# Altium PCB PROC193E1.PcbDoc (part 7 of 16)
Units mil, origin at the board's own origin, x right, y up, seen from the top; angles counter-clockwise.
Board outline 7700 x 2300 mil, 6 copper layers (Top Layer, GND 1, SIG 1, PWR, GND 2, Bottom Layer), stack 60.98 mil thick; 946 components, 667 nets, 9401 pads, 1730 vias.
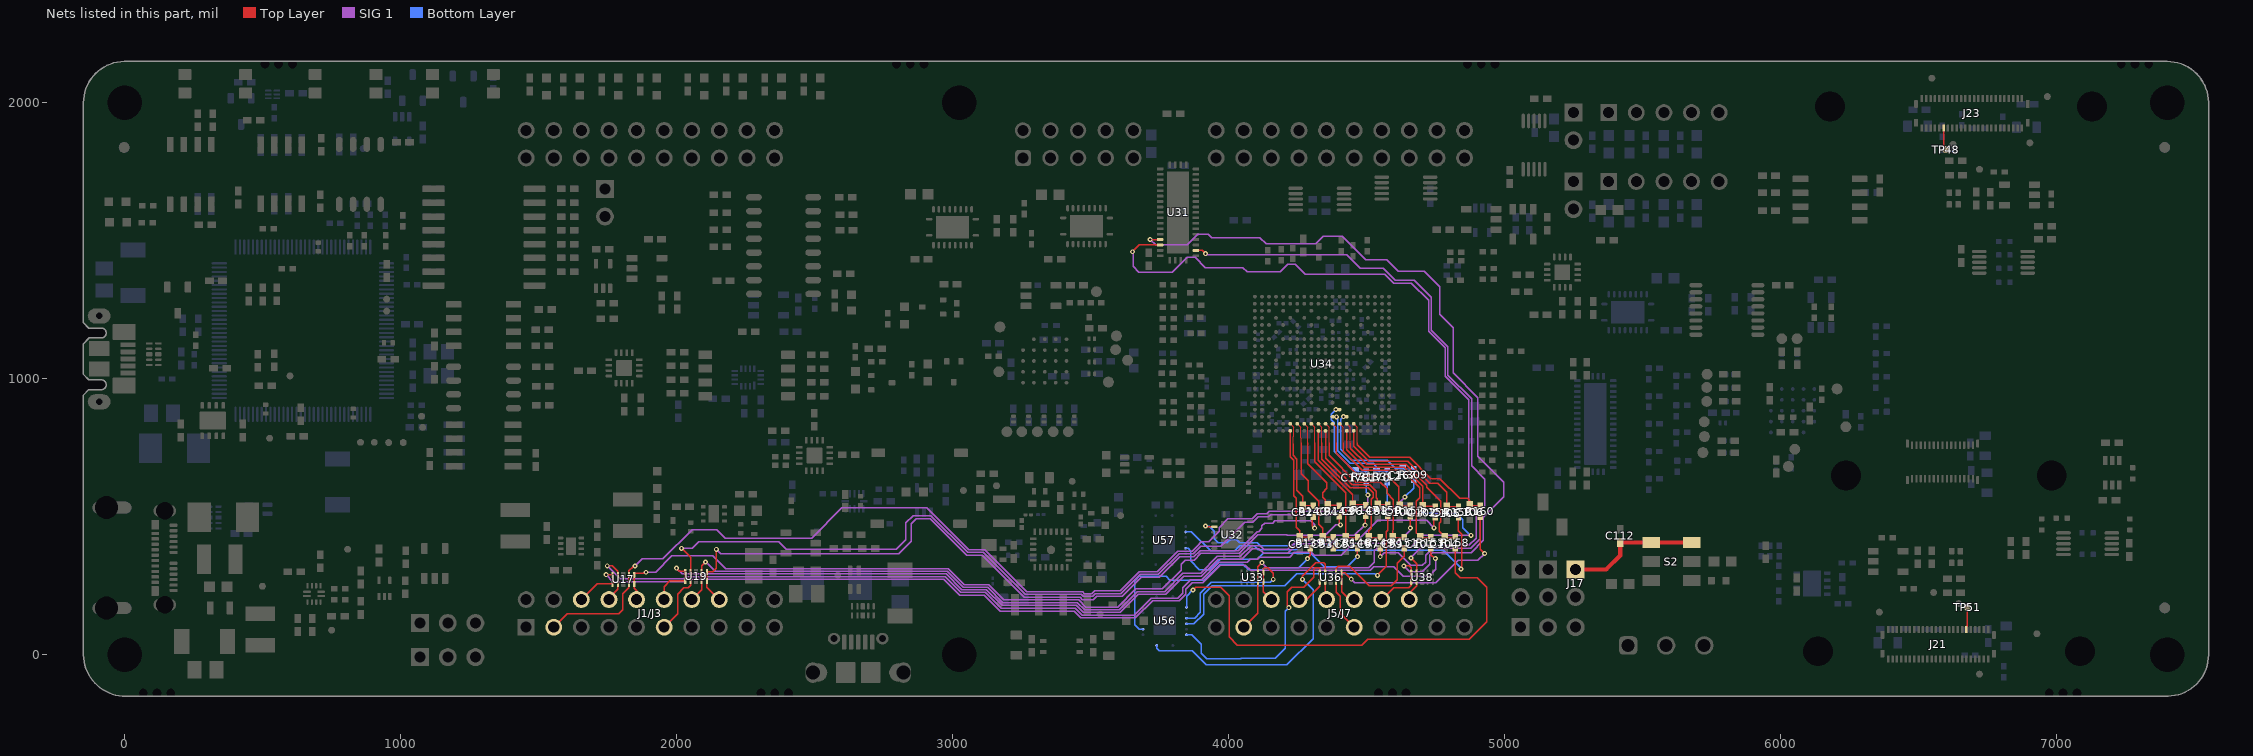
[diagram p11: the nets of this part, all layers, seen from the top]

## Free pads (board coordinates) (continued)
  round 4 on Mech16: 1(6059,2058) 1(6062.04,463.96) 1(6062.04,463.96) 1(6065.44,675.6) 1(6065.44,675.6) 1(6076,-115) 1(6076,-115) 1(6079.36,431.43) 1(6079.36,431.43) 1(6080.43,754.51) 1(6080.43,754.51) 1(6089.46,1050.69) 1(6089.46,1050.69) 1(6097.5,1257.86) 1(6097.5,1257.86) 1(6100.62,935.27) 1(6100.62,935.27) 1(6101.18,1357.83) 1(6101.18,1357.83) 1(6111,2109) 1(6111,2109) 1(6117.93,423.12) 1(6117.93,423.12) 1(6135.75,360.14) 1(6135.75,360.14) 1(6140,813) 1(6140,813) 1(6152.64,1260.32) 1(6152.64,1260.32) 1(6152.82,882.49) 1(6152.82,882.49) 1(6168.23,1013.42) 1(6168.23,1013.42) 1(6172.35,963.43) 1(6172.35,963.43) 1(6172.8,923.81) 1(6172.8,923.81) 1(6176,-115) 1(6176,-115) 1(6187,1583) 1(6187,1583) 1(6197.24,1674.12) 1(6197.24,1674.12) 1(6207.67,1013.42) 1(6207.67,1013.42) 1(6208.6,871.42) 1(6208.6,871.42) 1(6218,1593) 1(6218,1593) 1(6220.27,1553.27) 1(6220.27,1553.27) 1(6220.63,922.47) 1(6220.63,922.47) 1(6220.63,1211.87) 1(6220.63,1211.87) 1(6222.32,1172.87) 1(6222.32,1172.87) 1(6237.78,1675.15) 1(6237.78,1675.15) 1(6244.74,1374.44) 1(6244.74,1374.44) 1(6254.09,277.4) 1(6254.09,277.4) 1(6255,242) 1(6255,242) 1(6263.22,363.2) 1(6263.22,363.2) 1(6265.78,825.03) 1(6265.78,825.03) 1(6266.12,1223.61) 1(6266.12,1223.61) 1(6276,-115) 1(6276,-115) 1(6281,1538) 1(6281,1538) 1(6287.3,329.4) 1(6287.3,329.4) 1(6291.66,260.9) 1(6291.66,260.9) 1(6293.61,297.39) 1(6293.61,297.39) 1(6305,1762) 1(6305,1762) 1(6311,2109) 1(6311,2109) 1(6314,903) 1(6314,903) 1(6321.24,968.9) 1(6321.24,968.9) 1(6321.24,1051.32) 1(6321.24,1051.32) 1(6321.24,1151.35) 1(6321.24,1151.35) 1(6342.31,-83.37) 1(6342.31,-83.37) 1(6343,1641) 1(6343,1641) 1(6343.71,811.42) 1(6343.71,811.42) 1(6343.79,-42.49) 1(6343.79,-42.49) 1(6351.26,1608.66) 1(6351.26,1608.66) 1(6351.66,1578.24) 1(6351.66,1578.24) 1(6357.97,1758.31) 1(6357.97,1758.31) 1(6362,119.39) 1(6362,119.39) 1(6369.13,780.23) 1(6369.13,780.23) 1(6371.94,1649.6) 1(6371.94,1649.6) 1(6383.42,1161.63) 1(6383.42,1161.63) 1(6389,1048) 1(6389,1048) 1(6393.82,1330.03) 1(6393.82,1330.03) 1(6396,967) 1(6396,967) 1(6407.29,918.98) 1(6407.29,918.98) 1(6409.99,147.31) 1(6409.99,147.31) 1(6410.25,1007.84) 1(6410.25,1007.84) 1(6411.01,120.55) 1(6411.01,120.55) 1(6417.81,-87.19) 1(6417.81,-87.19) 1(6417.83,-45.04) 1(6417.83,-45.04) 1(6418.5,1875.1) 1(6418.5,1875.1) 1(6418.93,1091.76) 1(6418.93,1091.76) 1(6422.74,1913.01) 1(6422.74,1913.01) 1(6431.32,461.4) 1(6431.32,461.4) 1(6439.12,418.45) 1(6439.12,418.45) 1(6440.36,632.65) 1(6440.36,632.65) 1(6442.1,792.77) 1(6442.1,792.77) 1(6447.51,132.59) 1(6447.51,132.59) 1(6451.72,-47.64) 1(6451.72,-47.64) 1(6457.15,-87.19) 1(6457.15,-87.19) 1(6460.16,1871.6) 1(6460.16,1871.6) 1(6462.05,63) 1(6462.05,63) 1(6472.29,1331.83) 1(6472.29,1331.83) 1(6483.21,-47.64) 1(6483.21,-47.64) 1(6483.89,-87.19) 1(6483.89,-87.19) 1(6483.89,123.73) 1(6483.89,123.73) 1(6496.77,289.56) 1(6496.77,289.56) 1(6496.77,418.65) 1(6496.77,418.65) 1(6508.62,2104.04) 1(6508.62,2104.04) 1(6512.08,791.6) 1(6512.08,791.6) 1(6512.17,239.5) 1(6512.17,239.5) 1(6514.68,-87.19) 1(6514.68,-87.19) 1(6514.71,-47.64) 1(6514.71,-47.64) 1(6515.41,176.47) 1(6515.41,176.47) 1(6516,1502) 1(6516,1502) 1(6519,1768) 1(6519,1768) 1(6521.05,65) 1(6521.05,65) 1(6534.11,1852.25) 1(6534.11,1852.25) 1(6534.11,1879.65) 1(6534.11,1879.65) 1(6546.18,-87.19) 1(6546.18,-87.19) 1(6546.21,-47.64) 1(6546.21,-47.64) 1(6546.88,123.73) 1(6546.88,123.73) 1(6546.91,176.47) 1(6546.91,176.47) 1(6547.26,290.98) 1(6547.26,290.98) 1(6547.26,418.65) 1(6547.26,418.65) 1(6558.45,2049.91) 1(6558.45,2049.91) 1(6569.88,669.39) 1(6569.88,669.39) 1(6572.19,1789.93) 1(6572.19,1789.93) 1(6577.67,-87.19) 1(6577.67,-87.19) 1(6577.7,-47.64) 1(6577.7,-47.64) 1(6577.74,63.37) 1(6577.74,63.37) 1(6578.41,176.47) 1(6578.41,176.47) 1(6585.33,1951.64) 1(6585.33,1951.64) 1(6590.01,2090) 1(6590.01,2090) 1(6605.57,727.93) 1(6605.57,727.93) 1(6608,686) 1(6608,686) 1(6609.2,-47.64) 1(6609.2,-47.64) 1(6609.87,123.73) 1(6609.87,123.73) 1(6617.38,788.61) 1(6617.38,788.61) 1(6621.15,2090) 1(6621.15,2090) 1(6621.44,1879.92) 1(6621.44,1879.92) 1(6625.22,2049.35) 1(6625.22,2049.35) 1(6625.88,1950.65) 1(6625.88,1950.65) 1(6633.88,66.89) 1(6633.88,66.89) 1(6633.94,729.5) 1(6633.94,729.5) 1(6635.54,824.27) 1(6635.54,824.27) 1(6635.94,532.44) 1(6635.94,532.44) 1(6639.05,9) 1(6639.05,9) 1(6639.84,-80.81) 1(6639.84,-80.81) 1(6643.94,677.87) 1(6643.94,677.87) 1(6644.87,128.8) 1(6644.87,128.8) 1(6650,1827) 1(6650,1827) 1(6650.64,598.7) 1(6650.64,598.7) 1(6651.32,871.42) 1(6651.32,871.42) 1(6651.86,1503.22) 1(6651.86,1503.22) 1(6652.94,1879.92) 1(6652.94,1879.92) 1(6652.94,2050.04) 1(6652.94,2050.04) 1(6653,2090) 1(6653,2090) 1(6655.1,1387.02) 1(6655.1,1387.02) 1(6664.63,1131.82) 1(6664.63,1131.82) 1(6672.19,-47.64) 1(6672.19,-47.64) 1(6681.59,416.99) 1(6681.59,416.99) 1(6684.43,1879.92) 1(6684.43,1879.92) 1(6684.43,2050.04) 1(6684.43,2050.04) 1(6685.41,-86.1) 1(6685.41,-86.1) 1(6689,1834) 1(6689,1834) 1(6691.19,597.33) 1(6691.19,597.33) 1(6699.81,2090) 1(6699.81,2090) 1(6700.06,817.65) 1(6700.06,817.65) 1(6703.69,-47.64) 1(6703.69,-47.64) 1(6707.93,1713.56) 1(6707.93,1713.56) 1(6708.05,1592.26) 1(6708.05,1592.26) 1(6709.9,540.63) 1(6709.9,540.63) 1(6713.26,691.55) 1(6713.26,691.55) 1(6715.93,1801.72) 1(6715.93,1801.72) 1(6715.93,2049.35) 1(6715.93,2049.35) 1(6720,1337) 1(6720,1337) 1(6720.46,1108.48) 1(6720.46,1108.48) 1(6732.91,2090) 1(6732.91,2090) 1(6735.18,-47.64) 1(6735.18,-47.64) 1(6736.23,206.96) 1(6736.23,206.96) 1(6741,1946) 1(6741,1946) 1(6742.9,1823.8) 1(6742.9,1823.8) 1(6747.43,1879.92) 1(6747.43,1879.92) 1(6758.52,1713.44) 1(6758.52,1713.44) 1(6758.89,1588.61) 1(6758.89,1588.61) 1(6761.47,1847.69) 1(6761.47,1847.69) 1(6761.95,1369.47) 1(6761.95,1369.47) 1(6761.95,1402.77) 1(6761.95,1402.77) 1(6761.95,1441.9) 1(6761.95,1441.9) 1(6762.9,-78.84) 1(6762.9,-78.84) 1(6766.07,1476.9) 1(6766.07,1476.9) 1(6766.31,138.94) 1(6766.31,138.94) 1(6769.25,2050.35) 1(6769.25,2050.35) 1(6771,1772.8) 1(6771,1772.8) 1(6782.48,1949.68) 1(6782.48,1949.68) 1(6791.42,411.53) 1(6791.42,411.53) 1(6809.27,2089.76) 1(6809.27,2089.76) 1(6810.42,1879.92) 1(6810.42,1879.92) 1(6811.11,2050.04) 1(6811.11,2050.04) 1(6818,1843) 1(6818,1843) 1(6832.64,436.83) 1(6832.64,436.83) 1(6838,-113) 1(6838,-113) 1(6839.9,1992.32) 1(6839.9,1992.32) 1(6840.77,2089.76) 1(6840.77,2089.76) 1(6843.41,-47.3) 1(6843.41,-47.3) 1(6843.41,-12.15) 1(6843.41,-12.15) 1(6849.07,1875.92) 1(6849.07,1875.92) 1(6858.43,1349.46) 1(6858.43,1349.46) 1(6858.47,1497.59) 1(6858.47,1497.59) 1(6861.42,1849.7) 1(6861.42,1849.7) 1(6863.87,411.52) 1(6863.87,411.52) 1(6867.77,32.51) 1(6867.77,32.51) 1(6872.26,2089.76) 1(6872.26,2089.76) 1(6873.87,2050.5) 1(6873.87,2050.5) 1(6890.54,497.35) 1(6890.54,497.35) 1(6893,1962) 1(6893,1962) 1(6920.45,451.78) 1(6920.45,451.78) 1(6935.36,1422.22) 1(6935.36,1422.22) 1(6938,-113) 1(6938,-113) 1(6946,880) 1(6946,880) 1(6952,1154) 1(6952,1154) 1(6956.66,1703.75) 1(6956.66,1703.75) 1(6959.69,1387.53) 1(6959.69,1387.53) 1(6968.01,1907.59) 1(6968.01,1907.59) 1(6968.01,1949.02) 1(6968.01,1949.02) 1(6968.01,1987.22) 1(6968.01,1987.22) 1(6972.59,444.64) 1(6972.59,444.64) 1(6979.72,2110.52) 1(6979.72,2110.52) 1(6979.88,402.4) 1(6979.88,402.4) 1(6983.36,1422.45) 1(6983.36,1422.45) 1(7007.95,1669.53) 1(7007.95,1669.53) 1(7009.05,1630.16) 1(7009.05,1630.16) 1(7019.86,1504.79) 1(7019.86,1504.79) 1(7020.13,1553) 1(7020.13,1553) 1(7060.19,486.26) 1(7060.19,486.26) 1(7091.5,472.45) 1(7091.5,472.45) 1(7091.56,332.08) 1(7091.56,332.08) 1(7124.57,560.92) 1(7124.57,560.92) 1(7137.93,768.73) 1(7137.93,768.73) 1(7155.31,396.62) 1(7155.31,396.62) 1(7155.63,441.85) 1(7155.63,441.85) 1(7155.69,364.01) 1(7155.69,364.01) 1(7214.27,524.94) 1(7214.27,524.94) 1(7218,-110) 1(7218,-110) 1(7223.87,807.38) 1(7223.87,807.38) 1(7225.52,738.31) 1(7225.52,738.31) 1(7264.66,615.29) 1(7264.66,615.29) 1(7265.02,516.76) 1(7265.02,516.76) 1(7275.03,706.65) 1(7275.03,706.65) 1(7295.19,356.43) 1(7295.19,356.43) 1(7295.19,403.19) 1(7295.19,403.19) 1(7295.79,452.47) 1(7295.79,452.47) 1(7457,1861) 1(7457,1861) 1(7459,168) 1(7459,168) 1(7459,268) 1(7459,268) 1(7459,368) 1(7459,368) 1(7459,468) 1(7459,468) 1(7459,568) 1(7459,568) 1(7459,668) 1(7459,668) 1(7459,768) 1(7459,768) 1(7459,868) 1(7459,868) 1(7459,968) 1(7459,968) 1(7459,1068) 1(7459,1068) 1(7459,1168) 1(7459,1168) 1(7459,1268) 1(7459,1268) 1(7459,1368) 1(7459,1368) 1(7459,1468) 1(7459,1468) 1(7459,1568) 1(7459,1568) 1(7459,1668) 1(7459,1668) 1(7459,1768) 1(7459,1768) 1(7515,121) 1(7515,121) 1(7515,221) 1(7515,221) 1(7515,321) 1(7515,321) 1(7515,421) 1(7515,421) 1(7515,521) 1(7515,521) 1(7515,621) 1(7515,621) 1(7515,721) 1(7515,721) 1(7515,821) 1(7515,821) 1(7515,921) 1(7515,921) 1(7515,1021) 1(7515,1021) 1(7515,1121) 1(7515,1121) 1(7515,1221) 1(7515,1221) 1(7515,1321) 1(7515,1321) 1(7515,1421) 1(7515,1421) 1(7515,1521) 1(7515,1521) 1(7515,1621) 1(7515,1621) 1(7515,1721) 1(7515,1721) 1(7515,1821) 1(7515,1821)
  round 63 on Mech16: 1(0,0) 1(0,0) 1(0,2000) 1(0,2000) 1(3023.18,0) 1(3023.18,0) 1(3023.18,2000) 1(3023.18,2000) 1(7400,0) 1(7400,0) 1(7400,2000) 1(7400,2000)
  round 31.5 on Mech16: 1(0,0) 1(0,2000) 1(3023.18,0) 1(3023.18,2000) 1(7400,0) 1(7400,2000)
  round 3 on Mech16: 1(41.79,-148.2) 1(41.79,-148.2) 1(41.79,-148.2) 1(41.79,-148.2) 1(191.4,-148.2) 1(191.4,-148.2) 1(191.4,-148.2) 1(191.4,-148.2) 1(482.59,2150.26) 1(482.59,2150.26) 1(632.19,2150.26) 1(632.19,2150.26) 1(2279.79,-148.2) 1(2279.79,-148.2) 1(2429.4,-148.2) 1(2429.4,-148.2) 1(2771.26,2150.26) 1(2771.26,2150.26) 1(2920.86,2150.26) 1(2920.86,2150.26) 1(4517.79,-148.2) 1(4517.79,-148.2) 1(4667.4,-148.2) 1(4667.4,-148.2) 1(4839.92,2150.26) 1(4839.92,2150.26) 1(4989.53,2150.26) 1(4989.53,2150.26) 1(6947.79,-148.2) 1(6947.79,-148.2) 1(7097.4,-148.2) 1(7097.4,-148.2) 1(7208.59,2150.26) 1(7208.59,2150.26) 1(7208.59,2150.26) 1(7208.59,2150.26) 1(7247.96,2189.63) 1(7247.96,2189.63) 1(7247.96,2189.63) 1(7247.96,2189.63) 1(7318.82,2189.63) 1(7318.82,2189.63) 1(7318.82,2189.63) 1(7318.82,2189.63) 1(7358.19,2150.26) 1(7358.19,2150.26) 1(7358.19,2150.26) 1(7358.19,2150.26)
  round 1.5 on Mech16: 1(41.79,-148.2) 1(41.79,-148.2) 1(191.4,-148.2) 1(191.4,-148.2) 1(482.59,2150.26) 1(632.19,2150.26) 1(2279.79,-148.2) 1(2429.4,-148.2) 1(2771.26,2150.26) 1(2920.86,2150.26) 1(4517.79,-148.2) 1(4667.4,-148.2) 1(4839.92,2150.26) 1(4989.53,2150.26) 1(6947.79,-148.2) 1(7097.4,-148.2) 1(7208.59,2150.26) 1(7208.59,2150.26) 1(7247.96,2189.63) 1(7247.96,2189.63) 1(7318.82,2189.63) 1(7318.82,2189.63) 1(7358.19,2150.26) 1(7358.19,2150.26)
  round 16 on Mech16: 1(66.59,-138.2) 1(66.59,-138.2) 1(116.59,-138.2) 1(116.59,-138.2) 1(166.59,-138.2) 1(166.59,-138.2) 1(507.39,2140.26) 1(507.39,2140.26) 1(557.39,2140.26) 1(557.39,2140.26) 1(607.39,2140.26) 1(607.39,2140.26) 1(2304.59,-138.2) 1(2304.59,-138.2) 1(2354.59,-138.2) 1(2354.59,-138.2) 1(2404.59,-138.2) 1(2404.59,-138.2) 1(2796.06,2140.26) 1(2796.06,2140.26) 1(2846.06,2140.26) 1(2846.06,2140.26) 1(2896.06,2140.26) 1(2896.06,2140.26) 1(4542.59,-138.2) 1(4542.59,-138.2) 1(4592.59,-138.2) 1(4592.59,-138.2) 1(4642.59,-138.2) 1(4642.59,-138.2) 1(4864.73,2140.26) 1(4864.73,2140.26) 1(4914.73,2140.26) 1(4914.73,2140.26) 1(4964.73,2140.26) 1(4964.73,2140.26) 1(6972.59,-138.2) 1(6972.59,-138.2) 1(7022.59,-138.2) 1(7022.59,-138.2) 1(7072.59,-138.2) 1(7072.59,-138.2) 1(7233.39,2140.26) 1(7233.39,2140.26) 1(7283.39,2140.26) 1(7283.39,2140.26) 1(7333.39,2140.26) 1(7333.39,2140.26)
  round 8 on Mech16: 1(66.59,-138.2) 1(116.59,-138.2) 1(166.59,-138.2) 1(507.39,2140.26) 1(557.39,2140.26) 1(607.39,2140.26) 1(2304.59,-138.2) 1(2354.59,-138.2) 1(2404.59,-138.2) 1(2796.06,2140.26) 1(2846.06,2140.26) 1(2896.06,2140.26) 1(4542.59,-138.2) 1(4592.59,-138.2) 1(4642.59,-138.2) 1(4864.73,2140.26) 1(4914.73,2140.26) 1(4964.73,2140.26) 1(6972.59,-138.2) 1(7022.59,-138.2) 1(7072.59,-138.2) 1(7233.39,2140.26) 1(7283.39,2140.26) 1(7333.39,2140.26)
  round 7.87 on Mech16: 1(112.87,1053.49) 1(1595.06,417.3) 1(1771.11,265.47) 1(2034.38,276.01) 1(2158.71,486.82) 1(2638.57,151.52) 1(4050.48,273.46) 1(4404.52,289.21) 1(4735.74,289.21)
  round 15.75 on Mech16: 1(112.87,1053.49) 1(314.58,461.84) 1(1168.63,1097.63) 1(1595.06,417.3) 1(1771.11,265.47) 1(2034.38,276.01) 1(2158.71,486.82) 1(2280.62,983.5) 1(2638.57,151.52) 1(2669.41,536.84) 1(4002.75,671.68) 1(4050.48,273.46) 1(4404.52,289.21) 1(4735.74,289.21)
  round 11.81 on Mech16: 1(280.3,807.97) 1(455.07,539.37) 1(665.88,240.37) 1(1848.5,1010.01) 1(2459.32,751.68) 1(2655.9,243.94) 1(2936.96,1510.69) 1(3422.65,1514.81) 1(3981.31,489.61) 1(5247.89,1356.69) 1(5446.96,33.86) 1(5584.76,33.86) 1(5722.55,33.86) 1(6140.07,1722.87)
  round 23.62 on Mech16: 1(280.3,807.97) 1(405.34,934.21) 1(1848.5,1010.01) 1(2459.32,751.68) 1(2936.96,1510.69) 1(3422.65,1514.81) 1(3981.31,489.61) 1(5247.89,1356.69) 1(5446.96,33.86) 1(5446.96,33.86) 1(5507.5,1203.01) 1(5584.76,33.86) 1(5584.76,33.86) 1(5722.55,33.86) 1(5722.55,33.86) 1(6140.07,1722.87) 1(6153.46,296.1)
  round 3.94 on Mech16: 1(281.29,848.32) 1(281.29,848.32) 1(318.69,825.68) 1(318.69,825.68) 1(318.69,870.96) 1(318.69,870.96) 1(356.09,848.32) 1(356.09,848.32) 1(1616.72,372.03) 1(1616.72,372.03) 1(1616.72,415.33) 1(1616.72,415.33) 1(1790.43,1020.84) 1(1790.43,1020.84) 1(1790.43,1058.24) 1(1790.43,1058.24) 1(1827.83,1020.84) 1(1827.83,1020.84) 1(1827.83,1058.24) 1(1827.83,1058.24) 1(2134.1,488.78) 1(2134.1,488.78) 1(2134.1,532.09) 1(2134.1,532.09) 1(2479.99,703.45) 1(2479.99,703.45) 1(2479.99,740.85) 1(2479.99,740.85) 1(2517.39,703.45) 1(2517.39,703.45) 1(2517.39,740.85) 1(2517.39,740.85) 1(2948.77,1549.07) 1(2948.77,1549.07) 1(2998.97,1518.56) 1(2998.97,1518.56) 1(2998.97,1579.58) 1(2998.97,1579.58) 1(3049.17,1549.07) 1(3049.17,1549.07) 1(3340.16,378.98) 1(3340.16,378.98) 1(3371.74,378.98) 1(3371.74,378.98) 1(3434.46,1553.2) 1(3434.46,1553.2) 1(3484.65,1522.69) 1(3484.65,1522.69) 1(3484.65,1583.71) 1(3484.65,1583.71) 1(3534.85,1553.2) 1(3534.85,1553.2) 1(3785.57,1510.85) 1(3785.57,1510.85) 1(3785.57,1556.91) 1(3785.57,1556.91) 1(3785.57,1602.98) 1(3785.57,1602.98) 1(3785.57,1649.04) 1(3785.57,1649.04) 1(3785.57,1695.1) 1(3785.57,1695.1) 1(3816.08,1464.79) 1(3816.08,1464.79) 1(3816.08,1510.85) 1(3816.08,1510.85) 1(3816.08,1556.91) 1(3816.08,1556.91) 1(3816.08,1602.98) 1(3816.08,1602.98) 1(3816.08,1649.04) 1(3816.08,1649.04) 1(3816.08,1695.1) 1(3816.08,1695.1) 1(3816.08,1741.16) 1(3816.08,1741.16) 1(3846.59,1510.85) 1(3846.59,1510.85) 1(3846.59,1556.91) 1(3846.59,1556.91) 1(3846.59,1602.98) 1(3846.59,1602.98) 1(3846.59,1649.04) 1(3846.59,1649.04) 1(3846.59,1695.1) 1(3846.59,1695.1) 1(3985.24,434.49) 1(3985.24,434.49) 1(4012.8,397.09) 1(4012.8,397.09) 1(4012.8,471.9) 1(4012.8,471.9) 1(4040.36,434.49) 1(4040.36,434.49) 1(5189.82,1367.51) 1(5189.82,1367.51) 1(5189.82,1404.91) 1(5189.82,1404.91) 1(5227.22,1367.51) 1(5227.22,1367.51) 1(5227.22,1404.91) 1(5227.22,1404.91) 1(5297.57,743.9) 1(5297.57,743.9) 1(5297.57,789.97) 1(5297.57,789.97) 1(5297.57,836.03) 1(5297.57,836.03) 1(5297.57,882.09) 1(5297.57,882.09) 1(5297.57,928.16) 1(5297.57,928.16) 1(5328.08,697.84) 1(5328.08,697.84) 1(5328.08,743.9) 1(5328.08,743.9) 1(5328.08,789.97) 1(5328.08,789.97) 1(5328.08,836.03) 1(5328.08,836.03) 1(5328.08,882.09) 1(5328.08,882.09) 1(5328.08,928.16) 1(5328.08,928.16) 1(5328.08,974.22) 1(5328.08,974.22) 1(5358.59,743.9) 1(5358.59,743.9) 1(5358.59,789.97) 1(5358.59,789.97) 1(5358.59,836.03) 1(5358.59,836.03) 1(5358.59,882.09) 1(5358.59,882.09) 1(5358.59,928.16) 1(5358.59,928.16) 1(5395.29,1241.4) 1(5395.29,1241.4) 1(5445.49,1210.89) 1(5445.49,1210.89) 1(5445.49,1271.91) 1(5445.49,1271.91) 1(5495.68,1241.4) 1(5495.68,1241.4) 1(6090.47,257.71) 1(6090.47,257.71) 1(6113.11,220.31) 1(6113.11,220.31) 1(6113.11,295.11) 1(6113.11,295.11) 1(6135.75,257.71) 1(6135.75,257.71)
  round 1.25 on Mech16: 1(462.14,247.07) 1(501.86,784.53) 1(507.91,247.07) 1(547.63,784.53) 1(575.59,1010.35) 1(621.36,1010.35) 1(755.63,1668.93) 1(755.63,1812.54) 1(760.59,1663.96) 1(760.59,1817.51) 1(779.13,1718.96) 1(779.13,1718.96) 1(826.13,1718.96) 1(826.13,1718.96) 1(831.01,770) 1(857.12,1755) 1(876.78,770) 1(881.01,770) 1(902.88,1755) 1(926.78,770) 1(933.01,769) 1(943.58,1663.96) 1(943.58,1817.51) 1(948.54,1668.93) 1(948.54,1812.54) 1(978.78,769) 1(986.01,769) 1(1031.78,769) 1(1034.14,865) 1(1066.1,302.44) 1(1066.1,359.48) 1(1069.06,299.46) 1(1069.06,362.46) 1(1079.91,865) 1(1092.12,779.89) 1(1137.88,779.89) 1(1178.14,299.46) 1(1178.14,362.46) 1(1181.1,302.44) 1(1181.1,359.48) 1(1223.15,877.09) 1(1223.15,1060.08) 1(1228.11,872.13) 1(1228.11,1065.04) 1(1278.15,994.54) 1(1278.15,994.54) 1(1278.15,1041.54) 1(1278.15,1041.54) 1(1371.73,872.13) 1(1371.73,1065.04) 1(1376.69,877.09) 1(1376.69,1060.08) 1(1687.12,698.96) 1(1732.88,698.96) 1(1860.44,1344.77) 1(1860.44,1453.85) 1(1863.43,1341.81) 1(1863.43,1456.81) 1(1920.46,1341.81) 1(1920.46,1456.81) 1(1923.44,1344.77) 1(1923.44,1453.85) 1(2309.67,1292.52) 1(2309.67,1672.56) 1(2314.65,1287.54) 1(2314.65,1677.54) 1(2408.67,1311.04) 1(2408.67,1311.04) 1(2408.67,1358.04) 1(2408.67,1358.04) 1(2417.86,350.97) 1(2417.86,460.05) 1(2420.84,348.01) 1(2420.84,463.01) 1(2458.69,1287.54) 1(2458.69,1677.54) 1(2463.67,1292.52) 1(2463.67,1672.56) 1(2477.88,348.01) 1(2477.88,463.01) 1(2480.86,350.97) 1(2480.86,460.05) 1(2540.46,333.41) 1(2586.23,333.41) 1(2629.52,1710.51) 1(2675.29,1710.51) 1(2704.37,1715) 1(2750.14,1715) 1(3287.95,1246.22) 1(3287.95,1355.31) 1(3290.93,1243.26) 1(3290.93,1358.26) 1(3347.97,1243.26) 1(3347.97,1358.26) 1(3350.95,1246.22) 1(3350.95,1355.31) 1(3584.12,504) 1(3629.88,504) 1(4270.93,1705.67) 1(4270.93,1597.45) 1(4275.83,1710.56) 1(4275.83,1592.56) 1(4353.93,1613.56) 1(4381.93,1613.56) 1(4384.04,1592.56) 1(4384.04,1710.56) 1(4388.93,1597.45) 1(4388.93,1705.67) 1(4582.91,1636.42) 1(4582.91,1744.64) 1(4587.8,1631.53) 1(4587.8,1749.53) 1(4589.91,1728.53) 1(4617.91,1728.53) 1(4696.02,1631.53) 1(4696.02,1749.53) 1(4700.91,1636.42) 1(4700.91,1744.64) 1(4882.95,1523.67) 1(4882.95,1632.75) 1(4885.94,1520.71) 1(4885.94,1635.71) 1(4942.97,1520.71) 1(4942.97,1635.71) 1(4945.95,1523.67) 1(4945.95,1632.75) 1(5007.75,1531.58) 1(5007.75,1588.62) 1(5010.7,1528.6) 1(5010.7,1591.6) 1(5047.48,1792.54) 1(5047.48,1900.76) 1(5052.37,1787.65) 1(5052.37,1905.65) 1(5068.48,1794.65) 1(5068.48,1822.65) 1(5119.79,1528.6) 1(5119.79,1591.6) 1(5122.75,1531.58) 1(5122.75,1588.62) 1(5160.58,1787.65) 1(5160.58,1905.65) 1(5165.48,1792.54) 1(5165.48,1900.76) 1(5717.83,1158.94) 1(5717.83,1340.05) 1(5725.71,1151.07) 1(5725.71,1347.92) 1(5757.2,1292.8) 1(5757.2,1292.8) 1(5757.2,1324.3) 1(5757.2,1324.3) 1(5883.19,1151.07) 1(5883.19,1347.92) 1(5891.06,1158.94) 1(5891.06,1340.05) 1(5915.25,1363.04) 1(5955.53,944.72) 1(5961.02,1363.04) 1(6001.3,944.72) 1(6357.35,392.16) 1(6357.35,283.08) 1(6360.33,395.12) 1(6360.33,280.12) 1(6417.36,280.12) 1(6417.36,395.12) 1(6420.35,283.08) 1(6420.35,392.16) 1(6630.91,850.96) 1(6630.91,1000.96) 1(6655.91,825.96) 1(6655.91,1025.96) 1(6747.73,1476.88) 1(6747.73,1368.66) 1(6752.62,1481.77) 1(6752.62,1363.77) 1(6830.73,1384.77) 1(6833.26,1612.38) 1(6833.26,1721.47) 1(6836.24,1609.42) 1(6836.24,1724.42) 1(6858.73,1384.77) 1(6860.84,1363.77) 1(6860.84,1481.77) 1(6865.73,1368.66) 1(6865.73,1476.88) 1(6879.12,1855) 1(6893.27,1724.42) 1(6893.27,1609.42) 1(6896.26,1721.47) 1(6896.26,1612.38) 1(6924.88,1855) 1(6992.12,75) 1(7037.88,75) 1(7052.79,347.86) 1(7052.79,456.08) 1(7057.68,342.97) 1(7057.68,460.97) 1(7059.78,439.97) 1(7087.78,439.97) 1(7165.89,460.97) 1(7165.89,342.97) 1(7170.78,456.08) 1(7170.78,347.86) 1(7255.91,825.96) 1(7255.91,1025.96) 1(7280.91,850.96) 1(7280.91,1000.96)
  round 22.88 on Mech16: 1(485.03,247.07) 1(524.75,784.53) 1(598.48,1010.35) 1(853.9,770) 1(880,1755) 1(903.9,770) 1(955.9,769) 1(1008.9,769) 1(1057.03,865) 1(1115,779.89) 1(1710,698.96) 1(2563.35,333.41) 1(2652.41,1710.51) 1(2727.25,1715) 1(3607,504) 1(5938.14,1363.04) 1(5978.41,944.72) 1(6902,1855) 1(7015,75)
  round 45.77 on Mech16: 1(485.03,247.07) 1(524.75,784.53) 1(598.48,1010.35) 1(853.9,770) 1(880,1755) 1(903.9,770) 1(955.9,769) 1(1008.9,769) 1(1057.03,865) 1(1115,779.89) 1(1710,698.96) 1(2563.35,333.41) 1(2652.41,1710.51) 1(2727.25,1715) 1(3607,504) 1(5938.14,1363.04) 1(5978.41,944.72) 1(6902,1855) 1(7015,75)
  round 0.98 on Mech16: 1(521,2017.4) 1(526.57,2017.4) 1(7175.09,642.59) 1(7175.09,642.59) 1(7175.09,651.12) 1(7175.09,651.12)
  round 5.57 on Mech16: 1(523.79,2017.4)
  round 20 on Mech16: 1(1070.23,-8.36) 1(1070.23,-8.36) 1(1070.23,115.14) 1(1070.23,115.14) 1(1170.23,-8.36) 1(1170.23,-8.36) 1(1170.23,115.14) 1(1170.23,115.14) 1(1270.23,-8.36) 1(1270.23,-8.36) 1(1270.23,115.14) 1(1270.23,115.14) 1(1739.61,1587.95) 1(1739.61,1587.95) 1(1739.61,1687.95) 1(1739.61,1687.95) 1(5056.57,209.25) 1(5056.57,209.25) 1(5056.57,309.25) 1(5056.57,309.25) 1(5056.57,100) 1(5056.57,100) 1(5156.57,209.25) 1(5156.57,209.25) 1(5156.57,309.25) 1(5156.57,309.25) 1(5156.57,100) 1(5156.57,100) 1(5248.63,1614.55) 1(5248.63,1614.55) 1(5248.63,1714.55) 1(5248.63,1714.55) 1(5248.63,1864.55) 1(5248.63,1864.55) 1(5248.63,1964.55) 1(5248.63,1964.55) 1(5256.57,209.25) 1(5256.57,209.25) 1(5256.57,309.25) 1(5256.57,309.25) 1(5256.57,100) 1(5256.57,100) 1(5376.52,1714.55) 1(5376.52,1714.55) 1(5376.52,1964.55) 1(5376.52,1964.55) 1(5476.52,1714.55) 1(5476.52,1714.55) 1(5476.52,1964.55) 1(5476.52,1964.55) 1(5576.52,1714.55) 1(5576.52,1714.55) 1(5576.52,1964.55) 1(5576.52,1964.55) 1(5676.52,1714.55) 1(5676.52,1714.55) 1(5676.52,1964.55) 1(5676.52,1964.55) 1(5776.52,1714.55) 1(5776.52,1714.55) 1(5776.52,1964.55) 1(5776.52,1964.55)
  round 10 on Mech16: 1(1070.23,-8.36) 1(1070.23,115.14) 1(1170.23,-8.36) 1(1170.23,115.14) 1(1270.23,-8.36) 1(1270.23,115.14) 1(1739.61,1587.95) 1(1739.61,1687.95) 1(5056.57,209.25) 1(5056.57,309.25) 1(5056.57,100) 1(5156.57,209.25) 1(5156.57,309.25) 1(5156.57,100) 1(5248.63,1614.55) 1(5248.63,1714.55) 1(5248.63,1864.55) 1(5248.63,1964.55) 1(5256.57,209.25) 1(5256.57,309.25) 1(5256.57,100) 1(5376.52,1714.55) 1(5376.52,1964.55) 1(5476.52,1714.55) 1(5476.52,1964.55) 1(5576.52,1714.55) 1(5576.52,1964.55) 1(5676.52,1714.55) 1(5676.52,1964.55) 1(5776.52,1714.55) 1(5776.52,1964.55)
  round 1.57 on Mech16: 1(1160.76,1097.63) 1(1176.5,1097.63)
  round 20.08 on Mech16: 1(1454.17,100) 1(1454.17,100) 1(1454.17,200) 1(1454.17,200) 1(1454.17,1800) 1(1454.17,1800) 1(1454.17,1900) 1(1454.17,1900) 1(1554.17,100) 1(1554.17,100) 1(1554.17,200) 1(1554.17,200) 1(1554.17,1800) 1(1554.17,1800) 1(1554.17,1900) 1(1554.17,1900) 1(1654.17,100) 1(1654.17,100) 1(1654.17,200) 1(1654.17,200) 1(1654.17,1800) 1(1654.17,1800) 1(1654.17,1900) 1(1654.17,1900) 1(1754.17,100) 1(1754.17,100) 1(1754.17,200) 1(1754.17,200) 1(1754.17,1800) 1(1754.17,1800) 1(1754.17,1900) 1(1754.17,1900) 1(1854.17,100) 1(1854.17,100) 1(1854.17,200) 1(1854.17,200) 1(1854.17,1800) 1(1854.17,1800) 1(1854.17,1900) 1(1854.17,1900) 1(1954.17,100) 1(1954.17,100) 1(1954.17,200) 1(1954.17,200) 1(1954.17,1800) 1(1954.17,1800) 1(1954.17,1900) 1(1954.17,1900) 1(2054.17,100) 1(2054.17,100) 1(2054.17,200) 1(2054.17,200) 1(2054.17,1800) 1(2054.17,1800) 1(2054.17,1900) 1(2054.17,1900) 1(2154.17,100) 1(2154.17,100) 1(2154.17,200) 1(2154.17,200) 1(2154.17,1800) 1(2154.17,1800) 1(2154.17,1900) 1(2154.17,1900) 1(2254.17,100) 1(2254.17,100) 1(2254.17,200) 1(2254.17,200) 1(2254.17,1800) 1(2254.17,1800) 1(2254.17,1900) 1(2254.17,1900) 1(2354.17,100) 1(2354.17,100) 1(2354.17,200) 1(2354.17,200) 1(2354.17,1800) 1(2354.17,1800) 1(2354.17,1900) 1(2354.17,1900) 1(3954.17,100) 1(3954.17,100) 1(3954.17,200) 1(3954.17,200) 1(3954.17,1800) 1(3954.17,1800) 1(3954.17,1900) 1(3954.17,1900) 1(4054.17,100) 1(4054.17,100) 1(4054.17,200) 1(4054.17,200) 1(4054.17,1800) 1(4054.17,1800) 1(4054.17,1900) 1(4054.17,1900) 1(4154.17,100) 1(4154.17,100) 1(4154.17,200) 1(4154.17,200) 1(4154.17,1800) 1(4154.17,1800) 1(4154.17,1900) 1(4154.17,1900) 1(4254.17,100) 1(4254.17,100) 1(4254.17,200) 1(4254.17,200) 1(4254.17,1800) 1(4254.17,1800) 1(4254.17,1900) 1(4254.17,1900) 1(4354.17,100) 1(4354.17,100) 1(4354.17,200) 1(4354.17,200) 1(4354.17,1800) 1(4354.17,1800) 1(4354.17,1900) 1(4354.17,1900) 1(4454.17,100) 1(4454.17,100) 1(4454.17,200) 1(4454.17,200) 1(4454.17,1800) 1(4454.17,1800) 1(4454.17,1900) 1(4454.17,1900) 1(4554.17,100) 1(4554.17,100) 1(4554.17,200) 1(4554.17,200) 1(4554.17,1800) 1(4554.17,1800) 1(4554.17,1900) 1(4554.17,1900) 1(4654.17,100) 1(4654.17,100) 1(4654.17,200) 1(4654.17,200) 1(4654.17,1800) 1(4654.17,1800) 1(4654.17,1900) 1(4654.17,1900) 1(4754.17,100) 1(4754.17,100) 1(4754.17,200) 1(4754.17,200) 1(4754.17,1800) 1(4754.17,1800) 1(4754.17,1900) 1(4754.17,1900) 1(4854.17,100) 1(4854.17,100) 1(4854.17,200) 1(4854.17,200) 1(4854.17,1800) 1(4854.17,1800) 1(4854.17,1900) 1(4854.17,1900)
  round 10.04 on Mech16: 1(1454.17,100) 1(1454.17,200) 1(1454.17,1800) 1(1454.17,1900) 1(1554.17,100) 1(1554.17,200) 1(1554.17,1800) 1(1554.17,1900) 1(1654.17,100) 1(1654.17,200) 1(1654.17,1800) 1(1654.17,1900) 1(1754.17,100) 1(1754.17,200) 1(1754.17,1800) 1(1754.17,1900) 1(1854.17,100) 1(1854.17,200) 1(1854.17,1800) 1(1854.17,1900) 1(1954.17,100) 1(1954.17,200) 1(1954.17,1800) 1(1954.17,1900) 1(2054.17,100) 1(2054.17,200) 1(2054.17,1800) 1(2054.17,1900) 1(2154.17,100) 1(2154.17,200) 1(2154.17,1800) 1(2154.17,1900) 1(2254.17,100) 1(2254.17,200) 1(2254.17,1800) 1(2254.17,1900) 1(2354.17,100) 1(2354.17,200) 1(2354.17,1800) 1(2354.17,1900) 1(3954.17,100) 1(3954.17,200) 1(3954.17,1800) 1(3954.17,1900) 1(4054.17,100) 1(4054.17,200) 1(4054.17,1800) 1(4054.17,1900) 1(4154.17,100) 1(4154.17,200) 1(4154.17,1800) 1(4154.17,1900) 1(4254.17,100) 1(4254.17,200) 1(4254.17,1800) 1(4254.17,1900) 1(4354.17,100) 1(4354.17,200) 1(4354.17,1800) 1(4354.17,1900) 1(4454.17,100) 1(4454.17,200) 1(4454.17,1800) 1(4454.17,1900) 1(4554.17,100) 1(4554.17,200) 1(4554.17,1800) 1(4554.17,1900) 1(4654.17,100) 1(4654.17,200) 1(4654.17,1800) 1(4654.17,1900) 1(4754.17,100) 1(4754.17,200) 1(4754.17,1800) 1(4754.17,1900) 1(4854.17,100) 1(4854.17,200) 1(4854.17,1800) 1(4854.17,1900)
  round 0.69 on Mech16: 1(1587.19,417.3) 1(1602.94,417.3)
  round 1.38 on Mech16: 1(1587.19,417.3) 1(1602.94,417.3)
  round 19.68 on Mech16: 1(3254.17,1800) 1(3254.17,1800) 1(3254.17,1900) 1(3254.17,1900) 1(3354.17,1800) 1(3354.17,1800) 1(3354.17,1900) 1(3354.17,1900) 1(3454.17,1800) 1(3454.17,1800) 1(3454.17,1900) 1(3454.17,1900) 1(3554.17,1800) 1(3554.17,1800) 1(3554.17,1900) 1(3554.17,1900) 1(3654.17,1800) 1(3654.17,1800) 1(3654.17,1900) 1(3654.17,1900) 1(5664.36,294.53)
  round 15.62 on Mech16: 1(3633.19,-429.05)
  round 54 on Mech16: 1(6134.37,12.93) 1(6134.37,12.93) 1(6178.06,1987.07) 1(6178.06,1987.07) 1(6235.8,649.92) 1(6235.8,649.92) 1(6981.47,649.92) 1(6981.47,649.92) 1(7084.37,12.93) 1(7084.37,12.93) 1(7128.06,1987.07) 1(7128.06,1987.07)
  round 27 on Mech16: 1(6134.37,12.93) 1(6178.06,1987.07) 1(6235.8,649.92) 1(6981.47,649.92) 1(7084.37,12.93) 1(7128.06,1987.07)
  round 0.25 on Mech16: 1(6955.91,925.96)
  round 0.5 on Mech16: 1(6955.91,925.96)

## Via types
v1: diameter 18, hole 8, Top Layer to Bottom Layer, tented both sides, 1710 vias
v2: diameter 18, hole 8, Top Layer to Bottom Layer, tented top, 12 vias
v3: diameter 23.62, hole 11.81, Top Layer to Bottom Layer, tented both sides, 8 vias

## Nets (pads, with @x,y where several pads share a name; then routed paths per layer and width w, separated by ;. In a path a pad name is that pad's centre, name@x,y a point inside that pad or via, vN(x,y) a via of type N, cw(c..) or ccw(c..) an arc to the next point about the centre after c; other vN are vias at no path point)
1588_SFD: J21.38 TP51.1 | length 82.5
  Top Layer w5.3: J21.38@6672.53,91.39 6674.4,93.27 6674.4,104.04 6675.2,104.84 TP51.1@6675.2,172.83
1588_SFD1: J23.38 TP48.1 | length 81.1
  Top Layer w5.3: J23.38@6589.94,1908.44 6589.94,1843.22 6597.41,1835.75 TP48.1@6597.41,1830.42
ADC0_AIN2/GPIO46: J5/J7.63 U33.5 U33.6 U56.4 | length 606.1
  Top Layer w5.3: J5/J7.63@4154.17,200 4125.29,228.88 U33.5@4125.29,264.9 U33.6@4125.29,297.78 4125.29,311.34 4130.2,316.25 4140.75,316.25 4161.05,295.95 v1(4161.05,273.38)
  Bottom Layer w5.3: U56.4@3846.65,132.26 3876.27,132.26 3897.34,153.32 3897.34,173.94 3897.24,174.04 3897.24,223.3 3936.94,263 4150.67,263 v1(4161.05,273.38)
ADC1_AIN2/GPIO90: J5/J7.64 U36.5 U36.6 U56.7 | length 974.1
  Top Layer w5.3: v1(4217.57,170.59) 4217.57,174.03 4211.6,179.99 4211.6,228.56 4228.38,245.34 4272.32,245.34 4307.13,280.15 4307.13,309.13 4313.79,315.79 4326.45,315.79 4329.72,312.52 U36.5@4329.72,297.78 U36.6@4329.72,264.9 4329.72,248.73 4280.99,200 J5/J7.64@4254.17,200
  Bottom Layer w5.3: U56.7@3846.65,73.2 3866.25,73.2 3900.38,39.07 3900.38,5.61 3919.65,-13.66 4043.66,-13.66 4044.29,-13.04 4168.3,-13.04 4204.29,22.95 4204.29,157.32 v1(4217.57,170.59)
ADC1_AIN5/PR1_PRU0_GPIO1: J5/J7.67 U31.14 U38.5 U38.6 | length 2843.4
  Top Layer w5.3: v1(3715.1,1504.55) U31.14@3751.12,1504.55 ; J5/J7.67@4554.17,200 4597.14,242.97 4652.27,242.97 4660.94,251.64 U38.6@4660.94,264.9 U38.5@4660.94,297.78 U38.5@4660.94,302.05 ; v1(4634.12,322) 4653.57,322 4660.94,314.63 U38.5@4660.94,302.05 ; U38.5@4659.65,303.34 U38.5@4660.94,302.05
  SIG 1 w4.75: v1(3715.1,1504.55) 3734.77,1484.88 3849.03,1484.88 3888.23,1524.07 3925.03,1524.07 3937.48,1511.63 4112.3,1511.63 4134.95,1488.98 4314.41,1488.98 4342.62,1517.19 4411.71,1517.19 4496.82,1432.08 4571.83,1432.08 4614.39,1389.51 4707.75,1389.51 4764.36,1332.9 4764.36,1233.54 4812.67,1185.23 4812.67,1122.63 4812.52,1122.48 4812.52,1110.68 4812.67,1110.52 4812.67,1021.33 4902.79,931.21 4902.79,719.21 4996,626 4996,573 4921.94,498.94 4921.94,414.42 4877.87,370.34 4737.63,370.34 4727.88,360.59 4727.88,327.33 4701.35,300.81 4655.32,300.81 v1(4634.12,322)
ADC2_AIN2/GPIO106: J5/J7.65 U36.4 U36.7 U56.9 | length 1118
  Top Layer w5.3: v1(4266.83,273.61) 4266.83,285.39 4314.44,333 4344,333 4349.41,327.59 U36.4@4349.41,297.78 U36.7@4349.41,264.9 4349.41,204.76 J5/J7.65@4354.17,200
  Bottom Layer w5.3: U56.9@3738.39,33.83 3738.39,23.8 3747.94,14.25 3867.56,14.25 3867.94,14.25 3918.64,-36.45 4209.94,-36.45 4305.36,58.96 4305.36,235.08 v1(4266.83,273.61)
ADC2_AIN5/PR1_PRU0_GPIO2: J5/J7.68 U31.15 U38.4 U38.7 | length 2722.6
  Top Layer w5.3: v1(3650.99,1460.27) 3675.58,1484.87 U31.15@3751.12,1484.87 ; J5/J7.68@4654.17,200 4654.17,222.98 4680.62,249.43 U38.7@4680.62,264.9 U38.4@4680.62,297.78 4680.62,329.89 v1(4659.77,350.75)
  SIG 1 w4.75: v1(3650.99,1460.27) 3652.96,1458.31 3652.96,1408.07 3674.37,1386.66 3795.57,1386.66 3849.48,1440.57 3878.06,1440.57 3915.46,1403.17 4050.19,1403.17 4066.11,1387.25 4186.93,1387.25 4214.21,1414.53 4241.22,1414.53 4276.65,1379.1 4564.77,1379.1 4598.04,1345.83 4661.77,1345.83 4723.66,1283.94 4723.66,1172.23 4771.44,1124.45 4783.42,1112.46 4783.42,1011.07 4783.92,1010.57 4783.92,1009.42 4869.95,923.39 4869.95,538.97 4896.6,512.31 4896.6,422.67 4869.99,396.06 4705.09,396.06 v1(4659.77,350.75)
ADC_EXT_VREF: C112.1 J17.1 S2.3 S2.6 | length 488.2
  Top Layer w15: J17.1@5256.57,309.25 5367.34,309.25 5418.4,360.31 C112.1@5418.4,407.13 5530.6,407.13 S2.6@5530.99,406.73 S2.3@5676.66,406.73
AM261_ADC0_AIN0: J1/J3.23 R153.1 U17.1 U17.10 | length 3485
  Top Layer w5.3: J1/J3.23@1654.17,200 1711.08,256.9 U17.1@1767.17,256.9 U17.10@1767.17,289.78 1766.79,290.16 v1(1744.18,290.16) ; R153.1@4731.21,385.69 4731.21,363.24 4745.45,348.99 v1(4748.31,348.99)
  SIG 1 w4.75: v1(1744.18,290.16) 1744.18,289.2 1768.35,265.03 2027.43,265.03 2036.36,273.96 2967.99,273.96 3025.31,216.65 3114.16,216.65 3172.34,158.47 3439.35,158.47 3463.95,133.88 3661.79,133.88 3723.61,195.69 3820.17,195.69 3843.83,219.35 3843.83,238.12 3866.87,261.16 3904.82,261.16 3968.7,325.04 4059.93,325.04 4079.13,305.84 4513.28,305.84 4525.56,318.13 4598.26,318.13 4631.74,284.65 4725.92,284.65 4750.53,309.26 4750.53,346.77 v1(4748.31,348.99)
AM261_ADC0_AIN0_R: C101.2 R153.2 U34.W13 | length 665.8
  Top Layer w3.94: U34.W13@4401.57,836.97 4414.37,824.18 4414.37,767.84
  Top Layer w5.3: 4414.37,767.84 4414.37,737.32 4483.38,668.3 4627.56,668.3 4691.08,604.79 4691.08,585.05 4691.19,584.94 4691.19,568.77 4680.35,557.94 4680.35,557.56 4679.52,556.73 4679.52,441.19 4682.63,438.09 4684.85,438.09 4694.01,428.93 C101.2@4694.01,424.99 4731.14,424.99 R153.2@4731.21,425.06
AM261_ADC0_AIN1: J1/J3.2 R313.1 U17.4 U17.7 | length 3570.7
  Top Layer w5.3: J1/J3.2@1554.17,100 1603.31,149.13 1790.28,149.13 1804.01,162.86 1804.01,220.9 1826.22,243.11 U17.4@1826.22,256.9 U17.7@1826.22,289.78 ; U17.7@1826.26,289.81 1826.26,304.29 1841.49,319.52 1846.4,319.52 v1(1848.83,321.95)
  SIG 1 w4.75: v1(1848.83,321.95) 1874.32,347.44 1949.96,347.44 2055.49,452.97 2145.41,452.97 2175.52,422.87 2488.87,422.87 2598.21,532.21 2906.13,532.21 3058.09,380.25 3115.72,380.25 3267.55,228.42 3470.59,228.42 3476.97,222.04 3503.57,222.04 3513.44,231.91 3606.34,231.91 3675.24,300.81 3741.09,300.81 3760.47,320.19 3815.78,375.5 3866.72,375.5 3885.29,394.07 3885.39,394.07 3900.81,409.5 3926.5,409.5 3965.15,448.15 3965.15,461.15 3996.85,492.85 4085.31,492.85 4103.12,510.66 4137.47,510.66 4146.81,520 4405.42,520 4421.42,536 4487,536 4503.13,552.13 4503.13,578.52 v1(4503.77,579.16)
  Bottom Layer w5.3: R313.1@4498.12,624.66 4498.12,588.25 4503.77,582.6 v1(4503.77,579.16)
AM261_ADC0_AIN1_R: C178.2 R313.2 U34.U13 | length 324.1
  Top Layer w5.3: v1(4387.64,888.58) 4388.07,888.16 U34.U13@4401.57,888.16
  Bottom Layer w5.3: v1(4387.64,888.58) 4370.78,871.72 4370.78,852.32 4381.95,841.14 4381.95,767.84 4381.95,736.62 4444.83,673.74 4450.32,673.74 4459.48,664.58 C178.2@4459.48,664.29 4459.81,663.96 R313.2@4498.12,664.03
AM261_ADC0_AIN2: R158.1 U56.2 | length 1700.7
  Top Layer w5.3: v1(3869.97,234.86) 3880.14,245.03 3970,245.03 4001.3,213.72 4001.3,64.79 4030.77,35.32 4040.27,35.32 4226.68,35.32 4478.4,35.32 4482.52,35.32 4504.09,56.89 4872.04,56.89 4934.91,119.75 4934.91,243.88 4899.65,279.14 4838.29,279.14 4819.72,297.71 R158.1@4819.72,385.69
  Bottom Layer w5.3: U56.2@3846.65,171.63 3846.94,171.91 3846.94,211.83 v1(3869.97,234.86)
AM261_ADC0_AIN2_R: C104.2 R158.2 U34.W14 | length 684.3
  Top Layer w3.94: U34.W14@4427.16,836.97 4439.96,824.18 4439.96,782.88 4439.87,782.79 4439.87,767.84
  Top Layer w5.3: 4439.87,767.84 4439.87,748.98 4499.33,689.52 4641.42,689.52 4717.31,613.63 4717.31,607.37 4767.71,556.97 4767.71,481.34 4762.86,476.49 4762.86,447.62 4781.56,428.93 C104.2@4781.56,424.99 4819.66,424.99 R158.2@4819.72,425.06
AM261_ADC0_AIN3: J1/J3.6 R309.1 U19.2 U19.9 | length 3422
  Top Layer w5.3: J1/J3.6@1954.17,100 2002.86,148.68 2002.86,220.18 2025.91,243.23 2041.55,243.23 2050.11,251.79 U19.2@2050.13,267.45 ; v1(2017.2,385.96) 2050.13,353.03 U19.9@2050.13,300.32 U19.2@2050.13,267.45
  SIG 1 w4.75: v1(2017.2,385.96) 2055.74,385.96 2079.23,409.45 2369.35,409.45 2396.79,382.01 2795.96,382.01 2830.04,416.09 2830.04,478.35 2856.01,504.32 2920.59,504.32 3054.16,370.75 3110.92,370.75 3263,218.67 3465.71,218.67 3472.09,212.29 3507.61,212.29 3516.83,221.51 3609.38,221.51 3678.92,291.06 3744.77,291.06 3819.72,366 3870.75,366 3897.75,393 3971.04,393 4058.49,480.45 4086.45,480.45 4106.08,500.08 4143.36,500.08 4151.26,507.98 4411.34,507.98 4427.36,524 4590.07,524 v1(4637.71,571.65)
  Bottom Layer w5.3: v1(4637.71,571.65) 4637.71,572 4669.52,603.81 R309.1@4669.52,633.38
AM261_ADC0_AIN3_R: C167.2 R309.2 U34.V14 | length 426.5
  Top Layer w5.3: v1@4416.31,862.57 U34.V14@4427.16,862.57
  Bottom Layer w5.3: v1(4416.04,862.84) 4405.99,852.79 4405.99,744.65 4444.99,705.65 4573.62,705.65 4604.78,674.49 C167.2@4630.84,674.49 4632.58,672.75 R309.2@4669.52,672.75
AM261_ADC0_AIN4: J1/J3.26 R154.1 U19.1 U19.10 | length 3217.1
  Top Layer w5.3: J1/J3.26@1954.17,200 1954.17,246.72 1974.9,267.45 U19.1@2030.44,267.45 2030.44,302.33 2029.15,303.62 2008.69,303.62 v1(1998.65,313.65) ; v1(4743.34,460.26) 4743.34,493.51 R154.1@4747.35,497.51
  SIG 1 w4.75: v1(1998.65,313.65) 2019.34,292.96 2975.86,292.96 3033.18,235.65 3122.03,235.65 3178.44,179.24 3447.15,179.24 3473.01,153.38 3607.15,153.38 3672.7,218.92 3771.85,218.92 3837.18,284.25 3900.33,284.25 3962.47,346.38 4046.4,346.38 4085.14,385.13 4109.05,385.13 4127.06,367.12 4214.05,367.12 4248.41,401.48 4371.86,401.48 4388.51,418.13 4470.18,418.13 4539.03,486.98 4716.62,486.98 v1(4743.34,460.26)
AM261_ADC0_AIN4_R: C102.2 R154.2 U34.Y14 | length 517.3
  Top Layer w5.3: U34.Y14@4427.16,811.38 4427.16,742.71 4490.97,678.9 4634.99,678.9 4702.69,611.2 C102.2@4702.69,537.51 4746.72,537.51 R154.2@4747.35,536.88
AM261_ADC0_AIN5: J5/J7.66 R160.1 U36.1 U36.10 | length 844.2
  Top Layer w5.3: v1(4443.63,274.06) 4419.91,297.78 U36.1@4408.46,297.78 U36.10@4408.46,264.9 4408.46,229.3 4437.76,200 J5/J7.66@4454.17,200 ; R160.1@4911.17,500.63 4911.17,382.84 v1(4927.13,366.88)
  SIG 1 w4.75: v1(4443.63,274.06) 4456.33,261.36 4750.36,261.36 4831,342 4902.26,342 v1(4927.13,366.88)
AM261_ADC0_AIN5_R: C106.2 R160.2 U34.W15 | length 629
  Top Layer w3.94: U34.W15@4452.75,836.97 4465.55,824.18 4465.55,767.84
  Top Layer w5.3: 4465.55,767.84 4465.55,760.47 4510.92,715.09 4655.48,715.09 4732.24,638.34 4764.05,638.34 4836,566.39 4865.01,566.39 4873.26,558.14 C106.2@4873.26,540.61 4910.56,540.61 R160.2@4911.17,540
AM261_ADC0_AIN6: R159.1 U57.3 | length 1282
  Top Layer w5.3: R159.1@4832.2,497.51 4832.2,449.12 4844.62,436.7 4844.62,319.84 4843.68,318.9 4843.68,312.81 v1(4841.25,310.38)
  Bottom Layer w5.3: U57.3@3843.79,445.15 3863.31,445.15 3934.06,376.73 4021.24,376.73 4039.12,394.6 4092.17,394.6 4106.78,379.99 4243.07,379.99 4265.35,402.28 4359.1,402.28 4382.28,379.09 4776.76,379.09 4836.68,319.18 4836.68,318.39 4841.25,313.82 v1(4841.25,310.38)
AM261_ADC0_AIN6_R: C105.2 R159.2 U34.Y15 | length 557.3
  Top Layer w5.3: U34.Y15@4452.75,811.38 4452.75,755.86 4506.62,702 4648.95,702 4709.05,641.9 4728.51,622.43 4757.47,622.43 4790.1,589.8 C105.2@4790.1,536.45 4831.76,536.45 R159.2@4832.2,536.88
AM261_ADC1_AIN0: J1/J3.24 R152.1 U17.2 U17.9 | length 3350.1
  Top Layer w5.3: v1(1747.98,322.44) 1766.69,322.44 1785.83,303.3 1785.83,290.8 U17.9@1786.85,289.78 U17.2@1786.85,256.9 1786.85,237.52 1754.17,204.83 J1/J3.24@1754.17,200 ; v1(4657.76,459.03) 4658.15,459.42 R152.1@4658.15,501.36
  SIG 1 w4.75: v1(1747.98,322.44) 1794.34,276.08 2024.38,276.08 2031.76,283.46 2971.93,283.46 3029.24,226.15 3118.1,226.15 3174.76,169.49 3442.75,169.49 3468.62,143.62 3657.75,143.62 3719.57,205.44 3814.89,205.44 3832.96,223.52 3832.96,242.86 3862.61,272.52 3902.39,272.52 3965.7,335.83 4067.69,335.83 4077.99,346.13 4103.48,346.13 4110.23,352.87 4219.95,352.87 4238.02,370.94 4299.63,370.94 4310.1,360.47 4407.21,360.47 4450.62,403.88 4609.4,403.88 4655.23,449.7 4655.23,456.49 v1(4657.76,459.03)
AM261_ADC1_AIN0_R: C100.2 R152.2 U34.W12 | length 499.4
  Top Layer w3.94: U34.W12@4375.98,836.97 4388.78,824.18 4388.78,773.16 4388.69,773.07 4388.69,767.84
  Top Layer w5.3: 4388.69,767.84 4388.69,729.54 4471.13,647.1 4577.32,647.1 4616.32,608.1 4616.32,543.04 C100.2@4619.66,539.7 4657.13,539.7 R152.2@4658.15,540.73
AM261_ADC1_AIN1: J5/J7.42 R312.1 U33.4 U33.7 | length 1543.7
  Top Layer w5.3: J5/J7.42@4054.17,100 4105.6,151.43 U33.4@4105.6,264.9 U33.7@4105.6,297.78 4105.6,319.36 v1(4119.87,333.62)
  SIG 1 w4.75: v1(4119.87,333.62) 4137.48,316.01 4507.16,316.01 4526.65,335.49 4526.65,376.33 4542.05,391.73 4661.37,391.73 4702.48,432.84 v1(4877.35,432.84)
  Bottom Layer w5.3: R312.1@4573.38,624.92 4573.38,547.88 4607.77,513.49 4822.38,513.49 4846.95,488.93 4846.95,459.81 4873.92,432.84 v1(4877.35,432.84)
AM261_ADC1_AIN1_R: C170.2 R312.2 U34.V12 | length 358.7
  Top Layer w5.3: U34.V12@4375.89,862.66 4389.84,862.66 v1(4390.25,862.25)
  Bottom Layer w5.3: v1(4390.25,862.25) 4390.25,858.82 4394.95,854.12 4394.95,767.84 4394.95,739.18 4440.07,694.06 4523.1,694.06 4535.13,682.03 C170.2@4535.13,665.5 4536.34,664.29 R312.2@4573.38,664.29
AM261_ADC1_AIN2: R150.1 U56.5 | length 1043
  Top Layer w5.3: v1(4538.33,287.89) 4570.83,320.39 4570.83,445.1 4576.34,450.61 R150.1@4576.34,504.22
  Bottom Layer w5.3: U56.5@3846.65,112.57 3847.11,112.11 3873.41,112.11 3909.08,147.78 3909.08,218.7 3940.38,250 4203,250 4246.58,293.58 4529.21,293.58 4534.89,287.89 v1(4538.33,287.89)
AM261_ADC1_AIN2_R: C98.2 R150.2 U34.Y11 | length 417.1
  Top Layer w5.3: U34.Y11@4350.39,811.38 4350.39,712.9 4447.99,615.3 4511.05,615.3 4533.49,592.86 4533.49,592.05 4533.9,591.64 4533.9,569.07 4538.35,564.62 4538.35,544.22 C98.2@4539.23,543.34 ; C98.2@4542.48,543.59 R150.2@4576.34,543.59
AM261_ADC1_AIN3: J5/J7.46 R151.1 U36.2 U36.9 | length 626.3
  Top Layer w5.3: J5/J7.46@4454.17,100 4403.08,151.09 4403.08,211.96 4388.78,226.26 U36.9@4388.78,264.9 U36.2@4388.78,297.78 4388.78,313.19 4395.89,320.3 4438.33,320.3 4508.23,250.4 4588.05,250.4 4609.9,272.25 4609.9,330.96 4635.29,356.35 R151.1@4635.29,385.69
AM261_ADC1_AIN3_R: C99.2 R151.2 U34.W11 | length 609.5
  Top Layer w3.94: U34.W11@4350.39,836.97 4363.19,824.18 4363.19,767.84
  Top Layer w5.3: 4363.19,767.84 4363.19,722.49 4459.78,625.9 4548.25,625.9 4573.38,600.77 4573.38,585.5 4596.71,562.18 4596.71,452.23 4593.17,448.69 C99.2@4593.17,424.99 4635.22,424.99 R151.2@4635.29,425.06
AM261_ADC1_AIN4: J1/J3.27 R147.1 U19.4 U19.7 | length 2791.4
  Top Layer w5.3: J1/J3.27@2054.17,200 2089.5,235.32 U19.4@2089.5,267.45 U19.7@2089.5,300.32 2089.5,321.91 v1(2104.27,336.69) ; v1(4494.25,469.54) 4494.25,501.5 R147.1@4496.07,503.32
  SIG 1 w4.75: v1(2104.27,336.69) 2138.5,302.46 2979.8,302.46 3037.11,245.15 3125.97,245.15 3181.7,189.42 3450.96,189.42 3477.26,163.12 3603.11,163.12 3668.66,228.67 3767.04,228.67 3833.96,295.6 3897.89,295.6 3958.77,356.48 4042.14,356.48 4080.99,395.33 4113.2,395.33 4126,382.53 4214.49,382.53 4245.4,413.45 4363.68,413.45 4382.61,432.38 4455.34,432.38 4492.5,469.54 v1(4494.25,469.54)
AM261_ADC1_AIN4_R: C96.2 R147.2 U34.Y10 | length 366.3
  Top Layer w5.3: U34.Y10@4324.8,811.38 4324.8,795.85 4324.8,767.84 4324.8,704.28 4449.49,579.59 C96.2@4449.49,543.76 4495,543.76 R147.2@4496.07,542.69
AM261_ADC1_AIN5: R149.1 U31.23 | length 2357.5
  Top Layer w5.3: U31.23@3881.04,1465.18 3904,1465.18 v1(3915.76,1453.42) ; v1(4548.76,355.38) 4548.85,355.48 R149.1@4548.85,385.69
  SIG 1 w4.75: v1(3915.76,1453.42) 3920.14,1449.04 4427.11,1449.04 4475.75,1400.4 4559.64,1400.4 4602.76,1357.29 4672.37,1357.29 4733.93,1295.73 4733.93,1175.9 4793.17,1116.66 4793.17,1013.6 4879.45,927.33 4879.45,685 4928,636.45 4928,538 4910.16,520.16 4910.16,419.75 4875.8,385.39 4738.9,385.39 4713.35,359.85 4713.35,336.07 4701.18,323.89 4659.77,323.89 4613.47,370.19 4563.57,370.19 v1(4548.76,355.38)
AM261_ADC1_AIN5_R: C97.2 R149.2 U34.W10 | length 580.9
  Top Layer w3.94: U34.W10@4324.8,836.97 4337.6,824.18 4337.6,767.84
  Top Layer w5.3: 4337.6,767.84 4337.6,762.24 4337.51,762.15 4337.51,707.7 4440.51,604.7 4505.85,604.7 4523.3,587.25 4523.3,571.08 4516.64,564.42 4516.64,458.66 4507.2,449.22 C97.2@4507.2,424.99 4548.79,424.99 R149.2@4548.85,425.06
AM261_ADC1_AIN6: R146.1 U57.6 | length 766.5
  Top Layer w5.3: v1(4466.18,355.38) 4466.27,355.48 R146.1@4466.27,385.69
  Bottom Layer w5.3: U57.6@3843.79,386.1 3844.67,385.21 3852.7,385.21 3862.44,375.47 3862.44,339.93 3893.67,308.7 3931.33,308.7 3968.98,346.36 4103.36,346.36 4125.41,368.41 4296.5,368.41 4346.68,318.24 4429.03,318.24 v1(4466.18,355.38)
AM261_ADC1_AIN6_R: C95.2 R146.2 U34.W9 | length 505.6
  Top Layer w3.94: U34.W9@4299.21,836.97 4312,824.18 4312,767.84
  Top Layer w5.3: 4312,767.84 4312,699.81 4424.59,587.23 C95.2@4424.59,425.3 ; C95.2@4424.28,424.99 4466.21,424.99 R146.2@4466.27,425.06
AM261_ADC2_AIN0: J1/J3.25 R143.1 U17.5 U17.6 | length 2930.4
  Top Layer w5.3: J1/J3.25@1854.17,200 1854.17,232.19 1845.91,240.45 U17.5@1845.91,256.9 1845.91,294.78 1880.38,294.78 1884.73,299.13 v1(1888.17,299.13) ; R143.1@4400.37,501.22 4400.37,475.01 v1(4404.47,470.91)
  SIG 1 w4.75: v1(1888.17,299.13) 1922.85,299.13 1982.45,358.74 2129.92,358.74 2176.7,311.96 2983.73,311.96 3041.05,254.65 3129.9,254.65 3185.38,199.17 3456.02,199.17 3482.08,173.1 3597.46,173.1 3662.78,238.42 3759.69,238.42 3827.63,306.36 3827.63,328.63 3841.5,342.5 3874.12,342.5 3899.03,367.41 4037.24,367.41 4105.67,435.83 4209.76,435.83 4211.93,433.66 4349.87,433.66 4387.12,470.91 v1(4404.47,470.91)
AM261_ADC2_AIN0_R: C94.2 R143.2 U34.W8 | length 386.7
  Top Layer w3.94: U34.W8@4273.62,836.97 4286.41,824.18 4286.41,767.84
  Top Layer w5.3: 4286.41,767.84 4286.41,745.58 4286.15,745.31 4286.15,692.12 4355.75,622.52 4355.75,603.06 4340.15,587.45 4340.15,571.28 4349.95,561.48 4349.95,548.83 C94.2@4357.72,541.06 4399.89,541.06 R143.2@4400.37,540.59
AM261_ADC2_AIN2: R139.1 U56.11 | length 926
  Top Layer w5.3: v1(4285.57,348.35) 4285.57,349.53 4295.85,359.81 R139.1@4295.85,385.69
  Bottom Layer w5.3: U56.11@3689.17,92.88 3676.22,92.88 3659.33,109.78 3659.33,269.2 3674.42,284.29 3772.61,284.29 3786.49,270.41 3911.94,270.41 3970.15,328.63 4050.95,328.63 4072.27,307.31 4121.16,307.31 4130.1,316.25 4253.47,316.25 v1(4285.57,348.35)
AM261_ADC2_AIN2_R: C91.2 R139.2 U34.Y6 | length 439.8
  Top Layer w5.3: U34.Y6@4222.44,811.38 4222.44,767.84 4222.24,767.84 4222.24,762 4222.3,761.94 4222.3,760.98 4222.3,718.42 4235.71,705 4235.71,576.82 4244.81,567.72 4244.81,462.41 4257.17,450.04 C91.2@4257.17,424.99 4257.24,425.06 R139.2@4295.85,425.06
AM261_ADC2_AIN3: R142.1 U32.3 | length 606.9
  Top Layer w5.3: v1@3922.47,463.41 3947.23,463.41 U32.3@3947.84,464.02 ; R142.1@4377.79,385.69 4378.27,386.16 4394.08,386.16 4397.18,389.26 4397.18,398.18 v1(4396.48,398.88)
  Bottom Layer w5.3: v1(3915.71,466.73) 3916.23,466.21 3928.56,466.21 3947.84,446.92 3947.84,419.96 3961.8,406 3992.9,406 4004.37,417.46 4028.6,417.46 4039.25,406.8 4102.46,406.8 4113.36,395.89 4230.98,395.89 4250.71,415.63 4379.73,415.63 v1(4396.48,398.88)
AM261_ADC2_AIN3_R: C93.2 R142.2 U34.W7 | length 487.6
  Top Layer w3.94: U34.W7@4248.03,836.97 4260.82,824.18 4260.82,786.18 4262.78,784.22 4262.78,767.84
  Top Layer w5.3: 4262.78,767.84 4262.78,655.32 4287.9,630.19 4287.9,594.8 4326.14,556.56 4326.14,472.14 4340.27,458.01 C93.2@4340.27,424.99 ; C93.2@4340.34,425.06 R142.2@4377.79,425.06
AM261_ADC2_AIN4: J1/J3.28 R140.1 U19.5 U19.6 | length 2803.1
  Top Layer w5.3: v1(2143.24,382.33) 2143.24,313.44 2130.12,300.32 U19.6@2109.18,300.32 U19.5@2109.18,267.45 2109.18,244.99 J1/J3.28@2154.17,200 ; R140.1@4305.78,501.02 4302.5,497.75 4302.5,468.14 4311.13,459.51 v1(4311.13,458.69)
  SIG 1 w4.75: v1(2143.24,382.33) 2159.62,365.95 2804.31,365.95 2850.25,411.88 2850.25,474.94 2868.2,492.89 2918.58,492.89 3050.69,360.79 3106.3,360.79 3258.17,208.92 3460.91,208.92 3469.83,200 3509.1,200 3521.12,212.01 3613.31,212.01 3682.61,281.31 3748.66,281.31 3813.35,346 3822.48,355.13 3873.31,355.13 3895.8,377.62 4033.58,377.62 4102.37,446.41 4108.33,446.41 4119.65,457.73 4119.65,466.73 4130.41,477.49 4158.34,477.49 4167.21,486.36 4296.49,486.36 4311,471.86 4311,458.82 v1(4311.13,458.69)
AM261_ADC2_AIN4_R: C92.2 R140.2 U34.W6 | length 355.5
  Top Layer w3.94: U34.W6@4222.44,836.97 4235.23,824.18 4235.23,792.73 4232.84,790.34 4232.84,767.84 4232.84,765.43
  Top Layer w4.91: 4232.84,765.43 4232.9,765.37
  Top Layer w5.3: 4232.9,765.37 4232.9,722.81 4246.82,708.89 4246.82,595.95 4268.54,574.24 C92.2@4268.54,539.83 R140.2@4305.78,539.83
